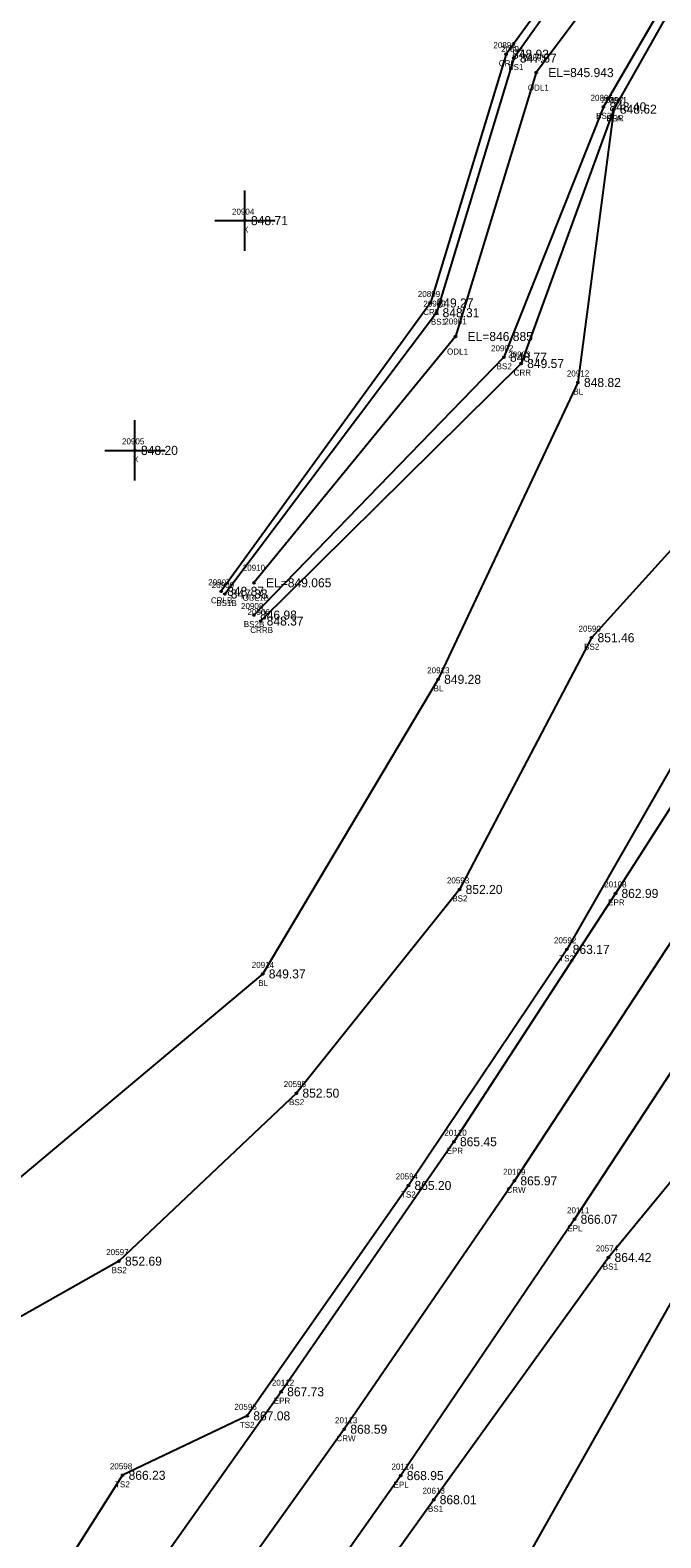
# Model space of a CAD drawing. Extents: x 1394668 to 1397182, y 1073212 to 1074501.
# Drawn here: x 1395697.6 to 1395802.6, y 1073687.4 to 1073938.1 of the extents above; entities that cross this region are included whole.
import ezdxf

# ---------------------------------------------------------------- set-up
doc = ezdxf.new("R2010")
doc.units = 0
for name, color, linetype in [('RD_DTM_BkLn1', 7, 'Continuous'), ('RD_DTM_BkLn2', 7, 'Continuous'), ('RD_DTM_BkLn_txCode', 7, 'Continuous'), ('RD_EX_H2O', 7, 'Continuous'), ('RD_EX_H2O_txCode', 7, 'Continuous'), ('RD_EX_Misc', 7, 'Continuous'), ('RD_EX_Misc_txCode', 7, 'Continuous'), ('RD_EX_Road', 7, 'Continuous'), ('RD_EX_Road_txCode', 7, 'Continuous'), ('RD_EX_TX_H2O_ELEV', 7, 'Continuous'), ('RD_EX_TX_Misc_ELEV', 7, 'Continuous'), ('RD_EX_TX_Road_ELEV', 7, 'Continuous'), ('RD_HC_Survey_ELEV', 7, 'Continuous'), ('RD_HC_Survey_txCode', 7, 'Continuous'), ('RD_SMD_Locator', 7, 'Continuous')]:
    doc.layers.add(name, color=color, linetype=linetype)

msp = doc.modelspace()

# ---------------------------------------------------------------- linework, layer by layer
at = {"layer": 'RD_DTM_BkLn1'}
for points in [[(1395794.76, 1073924.94), (1395788.78, 1073879.5), (1395765.52, 1073830.16), (1395736.34, 1073781.19), (1395672.02, 1073727.34), (1395621.2, 1073699.63)], [(1395880.09, 1073905.01), (1395858.99, 1073872.06), (1395832.15, 1073830.06), (1395805.49, 1073788.39), (1395778.2, 1073746.79), (1395749.91, 1073705.5), (1395721.01, 1073665.07), (1395690.33, 1073625.47), (1395658.02, 1073587.64), (1395622.95, 1073551.76), (1395585.52, 1073519.1), (1395545.34, 1073489.25), (1395503.34, 1073462.75), (1395459.17, 1073438.88), (1395413.72, 1073418.7), (1395366.56, 1073401.38), (1395319.05, 1073387), (1395269.86, 1073375.63), (1395220.56, 1073368.3)]]:
    msp.add_lwpolyline(points, dxfattribs=at)
at = {"layer": 'RD_DTM_BkLn2'}
for points in [[(1395865.63, 1073997.79), (1395800.04, 1073964.18), (1395778.12, 1073933.44), (1395765.25, 1073891.1), (1395730.01, 1073844.34)], [(1395870.08, 1073993.52), (1395808.8, 1073952.42), (1395793.02, 1073925.33), (1395776.47, 1073883.7), (1395734.88, 1073840.84)], [(1395878.8, 1073937.2), (1395844.48, 1073928.53), (1395822.57, 1073925.41), (1395808.65, 1073905.49), (1395815.82, 1073864.43), (1395791.04, 1073837.08), (1395769.09, 1073795.23), (1395741.94, 1073761.37), (1395712.42, 1073733.44), (1395686.92, 1073719.11), (1395655.83, 1073688.97), (1395630.94, 1073651.62), (1395607.03, 1073620.68), (1395575.39, 1073568.35), (1395560.35, 1073553.89), (1395550.78, 1073525.35), (1395509.42, 1073493.18)], [(1395872.29, 1073920.9), (1395859.76, 1073907.25), (1395840.82, 1073914.9), (1395825.1, 1073901.57), (1395832.07, 1073866.74), (1395834.98, 1073863.18), (1395809.97, 1073825.37), (1395786.91, 1073785.27), (1395760.58, 1073746.02), (1395733.77, 1073707.72), (1395713.02, 1073697.84), (1395686.96, 1073656.85), (1395662.51, 1073616.18), (1395631.74, 1073579.72), (1395598.58, 1073547.6), (1395556.36, 1073515.78), (1395517.25, 1073487.44)], [(1395908.34, 1073750.37), (1395886.37, 1073772.78), (1395863.64, 1073802.73), (1395854.1, 1073805.01), (1395826.05, 1073773.11), (1395793.87, 1073734.05), (1395764.78, 1073693.78), (1395736.01, 1073653.66), (1395704.56, 1073612.75), (1395670.33, 1073572.71), (1395637.43, 1073538.26), (1395595.47, 1073500.49), (1395545.21, 1073467.28)], [(1395908.75, 1073745.01), (1395882.18, 1073769.9), (1395863.69, 1073800.73), (1395855.74, 1073800.14), (1395835.34, 1073770.65), (1395805.16, 1073728.22), (1395777.09, 1073678.51), (1395754.62, 1073640.84), (1395721.66, 1073598.5), (1395682.88, 1073559.13), (1395644.57, 1073530.52), (1395608.93, 1073486.25), (1395561.12, 1073435.87)]]:
    msp.add_lwpolyline(points, dxfattribs=at)
at = {"layer": 'RD_EX_H2O'}
for points in [[(1395860.9, 1073995.76), (1395800.01, 1073966.01), (1395776.82, 1073934.08), (1395764.26, 1073892.72), (1395729.42, 1073844.79)], [(1395868.13, 1073995.29), (1395803.39, 1073959.78), (1395781.85, 1073931.02), (1395768.41, 1073887.15), (1395734.88, 1073846.21)], [(1395867.11, 1073990.5), (1395809.63, 1073951.26), (1395794.76, 1073924.94), (1395779.33, 1073882.65), (1395735.99, 1073839.85)]]:
    msp.add_lwpolyline(points, dxfattribs=at)
at = {"layer": 'RD_EX_Misc'}
for p, q in [((1395733.38, 1073901.41), (1395733.38, 1073911.41)), ((1395728.38, 1073906.41), (1395738.38, 1073906.41)), ((1395715.08, 1073863.22), (1395715.08, 1073873.22)), ((1395710.08, 1073868.22), (1395720.08, 1073868.22))]:
    msp.add_line(p, q, dxfattribs=at)
at = {"layer": 'RD_EX_Road'}
for points in [[(1395869.55, 1073911.71), (1395848.71, 1073878.81), (1395821.89, 1073836.43), (1395795.02, 1073794.57), (1395768.15, 1073753.29), (1395739.4, 1073711.73), (1395711.25, 1073671.91), (1395680.67, 1073632.3), (1395648.91, 1073595.47), (1395613.89, 1073559.5), (1395578.15, 1073528.43), (1395538.64, 1073499.26), (1395497.33, 1073473.22), (1395453.33, 1073449.12), (1395408.97, 1073429.57), (1395362.04, 1073412.34), (1395315.46, 1073398.44), (1395267.16, 1073387.31), (1395218.96, 1073380.11)], [(1395889.95, 1073898.5), (1395869.5, 1073865.35), (1395861.01, 1073852.28), (1395854.66, 1073843.33), (1395841.6, 1073823.61), (1395818.72, 1073786.86), (1395788.22, 1073740.4), (1395759.3, 1073697.79), (1395730.49, 1073656.98), (1395699.68, 1073617), (1395667.2, 1073579.48), (1395631.87, 1073543.45), (1395592.83, 1073509.92), (1395550.91, 1073478.97), (1395509.01, 1073452.5), (1395464.5, 1073428.26), (1395417.91, 1073407.56), (1395369.36, 1073389.54), (1395322.83, 1073375.66), (1395271.04, 1073363.5), (1395222.14, 1073356.32)]]:
    msp.add_lwpolyline(points, dxfattribs=at)
at = {"layer": 'RD_SMD_Locator'}
for centre in [(1395776.82, 1073934.08), (1395778.12, 1073933.44), (1395781.85, 1073931.02), (1395793.02, 1073925.33), (1395794.76, 1073924.94), (1395794.76, 1073924.94), (1395733.38, 1073906.41), (1395764.26, 1073892.72), (1395765.25, 1073891.1), (1395768.41, 1073887.15), (1395776.47, 1073883.7), (1395779.33, 1073882.65), (1395788.78, 1073879.5), (1395715.08, 1073868.22), (1395729.42, 1073844.79), (1395730.01, 1073844.34), (1395734.88, 1073846.21), (1395734.88, 1073840.84), (1395735.99, 1073839.85), (1395791.04, 1073837.08), (1395765.52, 1073830.16), (1395769.09, 1073795.23), (1395795.02, 1073794.57), (1395786.91, 1073785.27), (1395736.34, 1073781.19), (1395741.94, 1073761.37), (1395768.15, 1073753.29), (1395760.58, 1073746.02), (1395778.2, 1073746.79), (1395788.22, 1073740.4), (1395793.87, 1073734.05), (1395712.42, 1073733.44), (1395739.4, 1073711.73), (1395733.77, 1073707.72), (1395749.91, 1073705.5), (1395713.02, 1073697.84), (1395759.3, 1073697.79), (1395764.78, 1073693.78)]:
    msp.add_circle(centre, 0.15, dxfattribs=at)

# ---------------------------------------------------------------- texts
at = {"layer": 'RD_DTM_BkLn_txCode'}
for s, p in [('20894', (1395776, 1073934.44)), ('BS1', (1395777.18, 1073931.44)), ('20896', (1395790.88, 1073926.33)), ('20911', (1395793.21, 1073925.94)), ('BS2', (1395791.8, 1073923.33)), ('BLA', (1395793.52, 1073922.94)), ('20900', (1395763.06, 1073892.1)), ('BS1', (1395764.31, 1073889.1)), ('20902', (1395774.32, 1073884.7)), ('BS2', (1395775.25, 1073881.7)), ('20912', (1395786.94, 1073880.5)), ('BL', (1395788.02, 1073877.5)), ('20909', (1395727.85, 1073845.34)), ('BS1B', (1395728.59, 1073842.34)), ('20908', (1395732.72, 1073841.84)), ('BS2B', (1395733.18, 1073838.84)), ('20590', (1395788.88, 1073838.08)), ('BS2', (1395789.81, 1073835.08)), ('20913', (1395763.69, 1073831.16)), ('BL', (1395764.77, 1073828.16)), ('20593', (1395766.98, 1073796.23)), ('BS2', (1395767.87, 1073793.23)), ('20592', (1395784.79, 1073786.27)), ('TS2', (1395785.67, 1073783.27)), ('20914', (1395734.51, 1073782.19)), ('BL', (1395735.59, 1073779.19)), ('20595', (1395739.82, 1073762.37)), ('BS2', (1395740.71, 1073759.37)), ('20594', (1395758.46, 1073747.02)), ('TS2', (1395759.34, 1073744.02)), ('20597', (1395710.3, 1073734.44)), ('20574', (1395791.75, 1073735.05)), ('BS2', (1395711.19, 1073731.44)), ('BS1', (1395792.92, 1073732.05)), ('20596', (1395731.62, 1073708.72)), ('TS2', (1395732.52, 1073705.72)), ('20598', (1395710.9, 1073698.84)), ('TS2', (1395711.77, 1073695.84)), ('20613', (1395762.92, 1073694.78)), ('BS1', (1395763.83, 1073691.78))]:
    msp.add_text(s, height=1, dxfattribs=at).set_placement(p)
at = {"layer": 'RD_EX_H2O_txCode'}
for s, p in [('20893', (1395774.71, 1073935.08)), ('CRL', (1395775.6, 1073932.08)), ('20895', (1395779.73, 1073933.02)), ('ODL1', (1395780.44, 1073928.02)), ('20897', (1395792.65, 1073925.94)), ('CRR', (1395793.51, 1073922.94)), ('20899', (1395762.14, 1073893.72)), ('CRL', (1395763.03, 1073890.72)), ('20901', (1395766.54, 1073889.15)), ('ODL1', (1395767, 1073884.15)), ('20903', (1395777.17, 1073883.65)), ('CRR', (1395778.08, 1073880.65)), ('20910', (1395733.01, 1073848.21)), ('20907', (1395727.26, 1073845.79)), ('ODL1B', (1395733, 1073843.21)), ('CRLB', (1395727.72, 1073842.79)), ('20906', (1395733.8, 1073840.85)), ('CRRB', (1395734.26, 1073837.85))]:
    msp.add_text(s, height=1, dxfattribs=at).set_placement(p)
at = {"layer": 'RD_EX_Misc_txCode'}
for s, p in [('20904', (1395731.22, 1073907.41)), ('X', (1395733.06, 1073904.41)), ('20905', (1395712.92, 1073869.22)), ('X', (1395714.76, 1073866.22))]:
    msp.add_text(s, height=1, dxfattribs=at).set_placement(p)
at = {"layer": 'RD_EX_Road_txCode'}
for s, p in [('20108', (1395793.15, 1073795.57)), ('EPR', (1395793.8, 1073792.57)), ('20110', (1395766.55, 1073754.29)), ('EPR', (1395766.92, 1073751.29)), ('20111', (1395786.96, 1073741.4)), ('EPL', (1395787.02, 1073738.4)), ('20112', (1395737.85, 1073712.73)), ('EPR', (1395738.17, 1073709.73)), ('20114', (1395757.75, 1073698.79)), ('EPL', (1395758.09, 1073695.79))]:
    msp.add_text(s, height=1, dxfattribs=at).set_placement(p)
at = {"layer": 'RD_EX_TX_H2O_ELEV'}
for s, p in [('848.93', (1395777.82, 1073933.33)), ('EL=845.943', (1395783.85, 1073930.27)), ('848.62', (1395795.76, 1073924.19)), ('849.27', (1395765.26, 1073891.97)), ('EL=846.885', (1395770.41, 1073886.4)), ('849.57', (1395780.33, 1073881.9)), ('EL=849.065', (1395736.88, 1073845.46)), ('848.87', (1395730.42, 1073844.04)), ('848.37', (1395736.99, 1073839.1))]:
    msp.add_text(s, height=1.5, dxfattribs=at).set_placement(p)
at = {"layer": 'RD_EX_TX_Misc_ELEV'}
for s, p in [('847.67', (1395779.12, 1073932.69)), ('848.40', (1395794.02, 1073924.58)), ('848.62', (1395795.76, 1073924.19)), ('848.71', (1395734.38, 1073905.66)), ('848.31', (1395766.25, 1073890.35)), ('848.77', (1395777.47, 1073882.95)), ('848.82', (1395789.78, 1073878.75)), ('848.20', (1395716.08, 1073867.47)), ('847.38', (1395731.01, 1073843.59)), ('846.98', (1395735.88, 1073840.09)), ('851.46', (1395792.04, 1073836.33)), ('849.28', (1395766.52, 1073829.41)), ('852.20', (1395770.09, 1073794.48)), ('863.17', (1395787.91, 1073784.52)), ('849.37', (1395737.34, 1073780.44)), ('852.50', (1395742.94, 1073760.62)), ('865.20', (1395761.58, 1073745.27)), ('852.69', (1395713.42, 1073732.69)), ('864.42', (1395794.87, 1073733.3)), ('867.08', (1395734.77, 1073706.97)), ('866.23', (1395714.02, 1073697.09)), ('868.01', (1395765.78, 1073693.03))]:
    msp.add_text(s, height=1.5, dxfattribs=at).set_placement(p)
at = {"layer": 'RD_EX_TX_Road_ELEV'}
for s, p in [('862.99', (1395796.02, 1073793.82)), ('865.45', (1395769.15, 1073752.54)), ('866.07', (1395789.22, 1073739.65)), ('867.73', (1395740.4, 1073710.98)), ('868.95', (1395760.3, 1073697.04))]:
    msp.add_text(s, height=1.5, dxfattribs=at).set_placement(p)
at = {"layer": 'RD_HC_Survey_ELEV'}
for s, p in [('865.97', (1395779.2, 1073746.04)), ('868.59', (1395750.91, 1073704.75))]:
    msp.add_text(s, height=1.5, dxfattribs=at).set_placement(p)
at = {"layer": 'RD_HC_Survey_txCode'}
for s, p in [('20109', (1395776.33, 1073747.79)), ('CRW', (1395776.89, 1073744.79)), ('20113', (1395748.36, 1073706.5)), ('CRW', (1395748.6, 1073703.5))]:
    msp.add_text(s, height=1, dxfattribs=at).set_placement(p)

doc.saveas('drawing.dxf')
